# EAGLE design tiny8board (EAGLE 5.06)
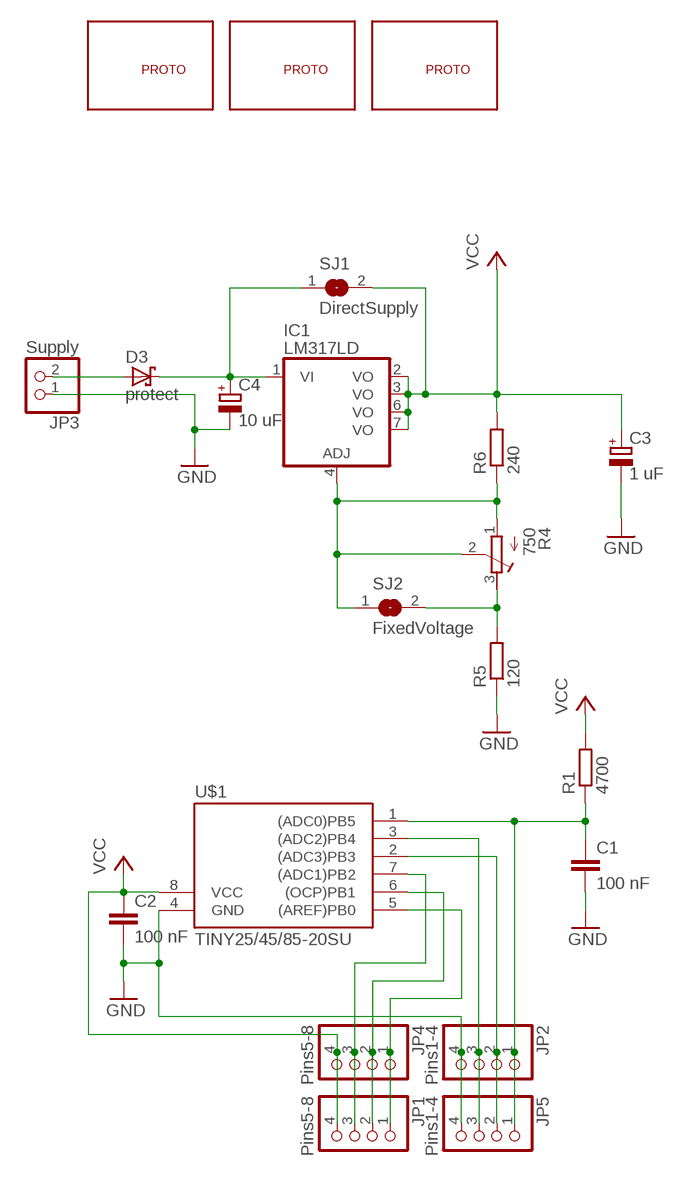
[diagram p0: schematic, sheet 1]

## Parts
C1  100 nF  C-EUC0805  [C0805]
C2  100 nF  C-EUC0805  [C0805]
C3  1 uF  CPOL-EU153CLV-0405  [153CLV-0405]
C4  10 uF  CPOL-EU153CLV-0405  [153CLV-0405]
D3  protect  SCHOTTKY-DIODESMD  [SMB]
IC1  LM317LD  [SO08]
JP1  Pins5-8  PINHD-1X4  [1X04]
JP2  Pins1-4  PINHD-1X4  [1X04]
JP3  Supply  PINHD-1X2  [1X02]
JP4  Pins5-8  PINHD-1X4  [1X04]
JP5  Pins1-4  PINHD-1X4  [1X04]
R1  4700  R-EU_R0805  [R0805]
R4  750  R-TRIMM3165W  [RTRIM3165W]
R5  120  R-EU_R0805  [R0805]
R6  240  R-EU_R0805  [R0805]
SJ1  DirectSupply  SJ  [SJ]
SJ2  FixedVoltage  SJ  [SJ]
U$1  TINY25/45/85-20SU  [SOIC8]
U$2  PROTO-AREA  [PROTO-AREA]
U$3  PROTO-AREA  [PROTO-AREA]  (not placed on a sheet)
U$4  PROTO-AREA  [PROTO-AREA]
U$5  PROTO-AREA  [PROTO-AREA]

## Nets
GND: C1.2 C2.2 C3.- C4.- JP2.4 JP3.1 JP5.4 R5.1 U$1.4(GND)
N$1: C1.1 JP2.1 JP5.1 R1.1 U$1.1((ADC0)PB5)
N$2: C4.+ D3.C IC1.1(VI) SJ1.1
N$3: JP1.1 JP4.1 U$1.5((AREF)PB0)
N$4: JP1.2 JP4.2 U$1.6((OCP)PB1)
N$5: JP1.3 JP4.3 U$1.7((ADC1)PB2)
N$6: JP2.2 JP5.2 U$1.2((ADC3)PB3)
N$8: JP2.3 JP5.3 U$1.3((ADC2)PB4)
N$9: D3.A JP3.2
N$10: R4.3(A) R5.2 SJ2.2
N$12: IC1.4(ADJ) R4.1(E) R4.2(S) R6.1 SJ2.1
VCC: C2.1 C3.+ IC1.2(VO) IC1.3(VO) IC1.6(VO) IC1.7(VO) JP1.4 JP4.4 R1.2 R6.2 SJ1.2 U$1.8(VCC)

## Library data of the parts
C1 C2 = rcl:C-EU: CAPACITOR, European symbol
C3 C4 = rcl:CPOL-EU: POLARIZED CAPACITOR, European symbol
D3 = diode:SCHOTTKY-DIODE: Schottky Diode
IC1 = linear:LM317LD: LOW CURRENT 1.2 TO 37V ADJUSTABLE VOLTAGE REGULATOR Source: http://pdf.alldatasheet.com
JP1 JP2 JP4 JP5 = pinhead:PINHD-1X4: PIN HEADER
JP3 = pinhead:PINHD-1X2: PIN HEADER
R1 R5 R6 = rcl:R-EU_: RESISTOR, European symbol
R4 = rcl:R-TRIMM: Trimm resistor
SJ1 SJ2 = jumper:SJ: SMD solder JUMPER
U$1 = avr-6:TINY25/45/85
U$2-U$5 = proto:PROTO-AREA

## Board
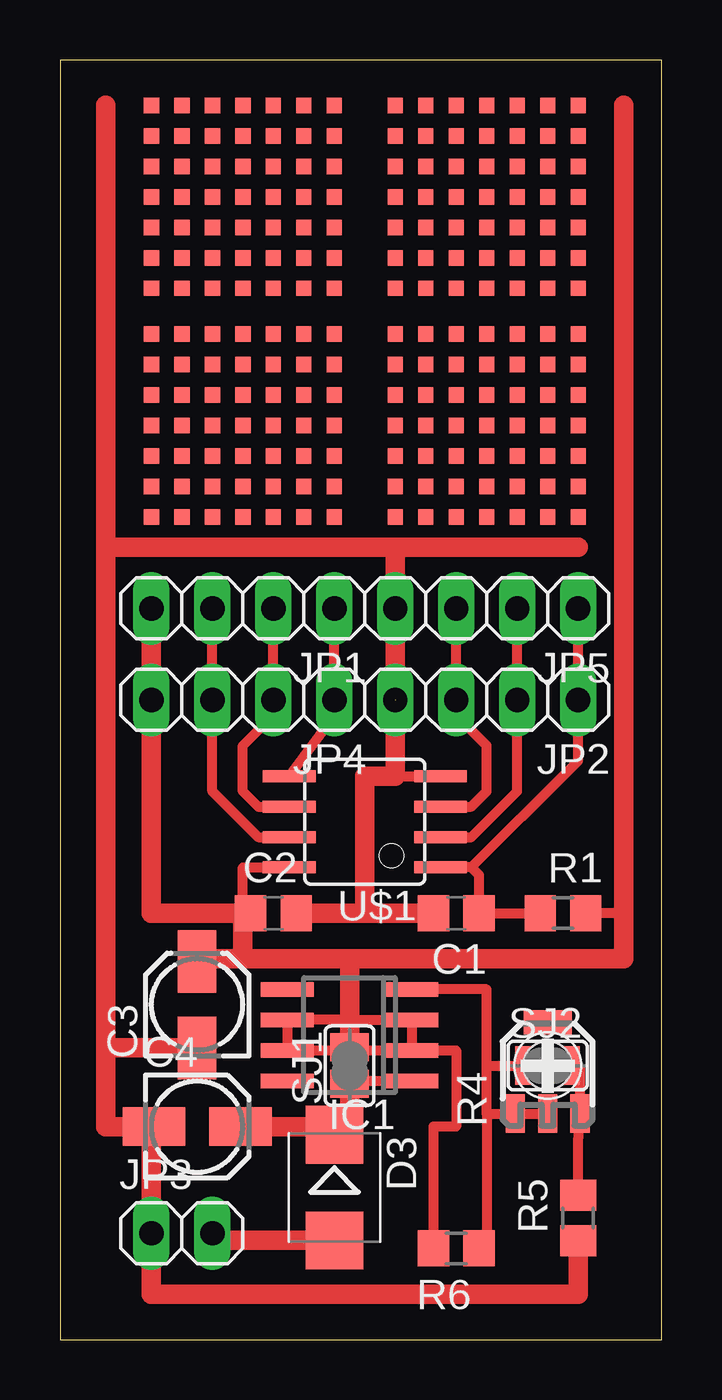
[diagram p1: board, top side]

Size 25.07 x 53.33 mm. Coordinates in mm from the lower left corner, seen from the top.
Outline: 0,0 25.07,0 25.07,53.33 0,53.33 0,0
Copper layers (1*16): Top 0.035mm / dielectric 1.5mm / Bottom 0.035mm
Design rules "default": minimum track width 10mil, minimum drill 24mil, track to track 8mil, track to pad 8mil, pad to pad 8mil, via to via 8mil, smd to smd 8mil, copper to edge 40mil, drill to drill 8mil, minimum pad ring 10mil, minimum via ring 8mil, stop-mask expansion 4mil, vias tented up to drill 0mil, thermal gap 10mil

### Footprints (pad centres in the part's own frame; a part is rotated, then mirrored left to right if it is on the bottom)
C0805 = smd 1.3 x 1.5: 1 -0.95,0; 2 0.95,0
153CLV-0405 = smd 2.6 x 1.6: + 1.8,0; - -1.8,0
SMB = smd 2.4 x 2.4: A 2.2,0; C -2.2,0
SO08 = smd 0.6 x 2.2: 1 -1.905,-2.6; 2 -0.635,-2.6; 3 0.635,-2.6; 4 1.905,-2.6; 5 1.905,2.6; 6 0.635,2.6; 7 -0.635,2.6; 8 -1.905,2.6
1X04 = drill 1.016 long: 1 -3.81,0; 2 -1.27,0; 3 1.27,0; 4 3.81,0
1X02 = drill 1.016 long: 1 -1.27,0; 2 1.27,0
R0805 = smd 1.3 x 1.5: 1 -0.95,0; 2 0.95,0
RTRIM3165W = smd 0.8 x 1.6: 1 -1.35,-2; 2 0,-2; 3 1.35,-2 | smd 2 x 1: 4 0,1.8 | hole 2: 0,0
SJ = smd 1.168 x 1.6: 1 -0.762,0; 2 0.762,0
SOIC8 = smd 0.5 x 2.2: 1 -1.905,-3.154; 2 -0.645,-3.154; 3 0.625,-3.154; 4 1.895,-3.154; 5 1.905,3.154; 6 0.635,3.154; 7 -0.635,3.154; 8 -1.905,3.154
PROTO-AREA = smd 0.635 x 0.635: P$2 -3.81,3.81; P$3 -2.54,3.81; P$4 -2.54,2.54; P$5 -3.81,2.54; P$6 -1.27,3.81; P$7 -1.27,2.54; P$8 0,2.54; P$9 0,3.81; P$10 1.27,3.81; P$11 1.27,2.54; P$12 2.54,2.54; P$13 2.54,3.81; P$14 -3.81,1.27; P$15 -2.54,1.27; P$16 -1.27,1.27; P$17 0,1.27; P$18 1.27,1.27; P$19 2.54,1.27; P$20 2.54,0; P$21 1.27,0; P$22 0,0; P$23 -1.27,0; P$24 -2.54,0; P$25 -3.81,0; P$26 -3.81,-1.27; P$27 -2.54,-1.27; P$28 -1.27,-1.27; P$29 0,-1.27; P$30 1.27,-1.27; P$31 2.54,-1.27; P$32 2.54,-2.54; P$33 1.27,-2.54; P$34 0,-2.54; P$35 -1.27,-2.54; P$36 -2.54,-2.54; P$37 -3.81,-2.54; P$38 -3.81,-3.81; P$39 -2.54,-3.81; P$40 -1.27,-3.81; P$41 0,-3.81; P$42 1.27,-3.81; P$43 2.54,-3.81; P$44 3.81,-3.81; P$45 3.81,-2.54; P$46 3.81,-1.27; P$47 3.81,0; P$48 3.81,1.27; P$49 3.81,2.54; P$50 3.81,3.81

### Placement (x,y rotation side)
C1  16.51,17.78 180 top
C2  8.89,17.78 0 top
C3  5.71,13.97 90 top
C4  5.71,8.89 0 top
D3  11.43,6.35 270 top
IC1  12.06,12.7 90 top
JP1  7.62,30.48 180 top
JP2  17.78,26.67 180 top
JP3  5.08,4.45 0 top
JP4  7.62,26.67 180 top
JP5  17.78,30.48 180 top
R1  20.96,17.78 0 top
R4  20.32,11.43 0 top
R5  21.59,5.08 90 top
R6  16.51,3.81 180 top
SJ1  12.06,11.43 90 top
SJ2  20.32,11.43 0 top
U$1  12.7,21.59 90 top
U$2  7.62,38.1 0 top
U$3  17.78,38.1 0 top
U$4  7.62,47.62 0 top
U$5  17.78,47.62 0 top

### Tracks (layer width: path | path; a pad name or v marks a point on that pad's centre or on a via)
GND  (1 unrouted)
  Top 0.406: C2.2 10.16,17.78 | 3.81,8.79 C4.- | U$1.4 13.33,23.49 13.33,23.5 13.34,23.5 13.97,23.49
  Top 0.813: 10.16,17.78 12.7,17.78 | 12.7,17.78 C1.2 | 13.96,26.66 13.96,24.12 13.97,23.49 12.7,23.5 12.7,17.78 | 3.81,8.79 JP3.1 3.81,1.91 21.59,1.91 R5.1 | JP2.4 JP5.4 13.97,33.02 1.91,33.02 | 1.91,12.06 1.91,8.89 C4.- | 1.91,12.06 1.91,33.02 | 1.91,33.02 1.91,51.43 | C3.- 1.91,12.17 1.91,12.06 | 1.91,33.02 21.59,33.02 | C2.2 12.7,17.78
N$1
  Top 0.406: JP5.1 JP2.1 21.59,24.13 21.27,23.81 | 17.15,19.69 U$1.1 | 17.15,19.69 21.27,23.81 | 17.15,19.69 17.46,19.37 C1.1 R1.1 | 21.27,23.81 20.96,23.5
N$2
  Top 0.406: SJ1.1 12.06,10.79 IC1.1 | D3.C 11.43,8.89
  Top 0.813: D3.C 11.09,8.89 C4.+ | 12.06,10.79 12.06,8.89 11.43,8.89
N$3
  Top 0.406: U$1.5 11.43,26.01 JP4.1 JP1.1
N$4
  Top 0.406: U$1.6 8.26,22.23 7.62,22.86 7.62,24.77 8.89,26.04 JP4.2 JP1.2
N$5
  Top 0.406: U$1.7 8.26,20.96 6.35,22.86 JP4.3 JP1.3
N$6
  Top 0.406: U$1.2 17.15,20.96 19.05,22.86 JP2.2 JP5.2
N$7
  Top 0.406: 9.53,12.06 14.61,12.06
N$8
  Top 0.406: U$1.3 17.15,22.23 17.78,22.86 17.78,24.77 16.51,26.04 JP2.3 JP5.3
N$9
  Top 0.813: JP3.2 6.64,4.15 D3.A
N$10
  Top 0.406: R5.2 21.59,8.26 21.67,9.45 | R4.3 21.67,9.45 | 21.67,9.45 21.67,11.35 21.59,11.43 SJ2.2
N$12
  Top 0.406: 17.78,11.43 SJ2.1 | 17.78,11.43 17.78,14.61 IC1.4 | R4.2 R4.1 17.78,9.43 | 17.78,9.43 17.78,11.43 | 17.78,9.43 17.78,3.81 R6.1
VCC
  Top 0.406: IC1.7 IC1.6 12.06,13.33 IC1.3 IC1.2 16.51,12.06 16.51,8.89 15.56,8.89 R6.2 | C2.1 7.94,18.12 7.62,18.12 7.62,19.69 U$1.8 | JP1.4 3.81,31.75 | 23.5,17.78 R1.2
  Top 0.813: JP1.4 JP4.4 3.81,17.78 7.62,17.78 | SJ1.2 12.06,13.33 12.06,15.88 | 12.06,15.88 21.06,15.88 | 21.06,15.88 20.96,15.88 | 21.06,15.88 23.5,15.88 23.5,17.78 23.5,51.43 | 7.62,15.88 12.06,15.88 | 7.62,15.88 7.62,17.78 | 7.62,17.78 C2.1 | 7.62,15.88 5.71,15.88 C3.+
